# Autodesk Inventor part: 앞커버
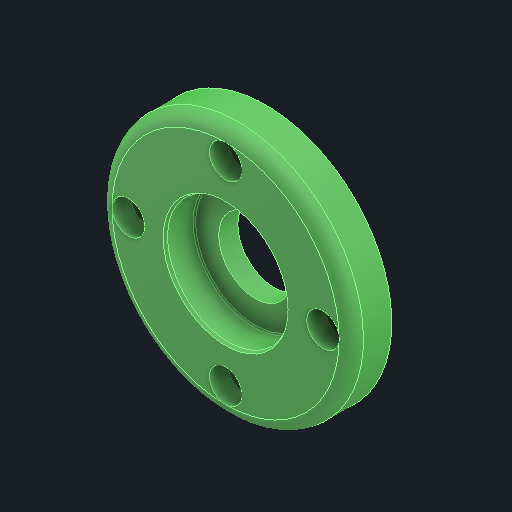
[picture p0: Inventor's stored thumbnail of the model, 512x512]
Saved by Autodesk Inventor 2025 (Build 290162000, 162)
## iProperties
Created: 2025-08
Part Number: 앞커버
Material: 알루미늄 6061
Document SubType Name: Modeling
Designer: infra005
Density: 2.71 g/cm^3
Appearance: 기본값
Author: jhkim
Sending System: Autodesk Inventor 2026
Preprocessor: ST-DEVELOPER v20.1
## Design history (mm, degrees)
feature "솔리드1"
node "솔리드2"
